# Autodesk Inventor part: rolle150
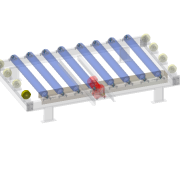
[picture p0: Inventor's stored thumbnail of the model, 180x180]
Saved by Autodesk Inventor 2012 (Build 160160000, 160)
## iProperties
Company: CAD-Verlag
Part Number: rolle150
Document SubType Name: Modeling
Created: 2004-09
Material: Standard
Designer: Greiling
Manufacturer: Standard
Standards Organization: Custom
Density: 1 g/cm^3
Control State: 0
Master: False
Checked Out: False
Shininess: 64.0
Length Units: 11269
Angle Units: 11279
Time Units: 11290
Mass Units: 11283
Length Display Precision: 3
Angle Display Precision: 2
Compacted: True
Density: 0.0
Volumn: 0.0
Area: 0.0
PropertySet Name: Model Information
Author: Jürgen Kronas
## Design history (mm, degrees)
sketch "Skizze1"
  geometry: L1 (0, 120)-(0, -90) reference; L2 (-90, 0)-(120, 0) reference; L3 (-90, 0)-(120, 0) reference; L4 (0, -90)-(0, 120) reference; C1 r 75 at (0, 0); 1 further point
  constraints: 1 centre point, 1 coincident
  dimensions: "d0" = 150 diameter of C1
extrude "Extrusion1" new body sketch "Skizze1" distance "d1" = 50; taper "d2" = 0 deg
sketch "Skizze2"
  geometry: C1 r 75 at (0, 0) reference; 1 further point
  constraints: 1 coincident
hole "Bohrung1" sketch "Skizze2" at (0, 0) diameter "d3" = 21; stored, may be unused: countersink angle "d7" = 82 deg, drill point angle "d9" = 118 deg; dims "d4" = 6, "d5" = 4, "d6" = 2, "d8" = 8
sketch "Skizze3"
  geometry: C1 r 10.5 at (0, 0) reference; C2 r 75 at (0, 0) reference; C3 r 20 at (0, 0)
  constraints: 1 centre point, 1 coincident
  dimensions: "d10" = 40 diameter of C3
extrude "Extrusion2" join sketch "Skizze3" distance "d11" = 10; taper "d12" = 0 deg
sketch "Skizze4"
  geometry: C1 r 10.5 at (0, 0) reference; C2 r 75 at (0, 0) reference; C3 r 20 at (0, 0)
  constraints: 1 centre point, 1 coincident
  dimensions: "d13" = 40 diameter of C3
extrude "Extrusion3" join sketch "Skizze4" distance "d14" = 10; taper "d15" = 0 deg
node "Volumenkörper1"
node "Volumenkörpern"
node "Oberflächenkörpern"
